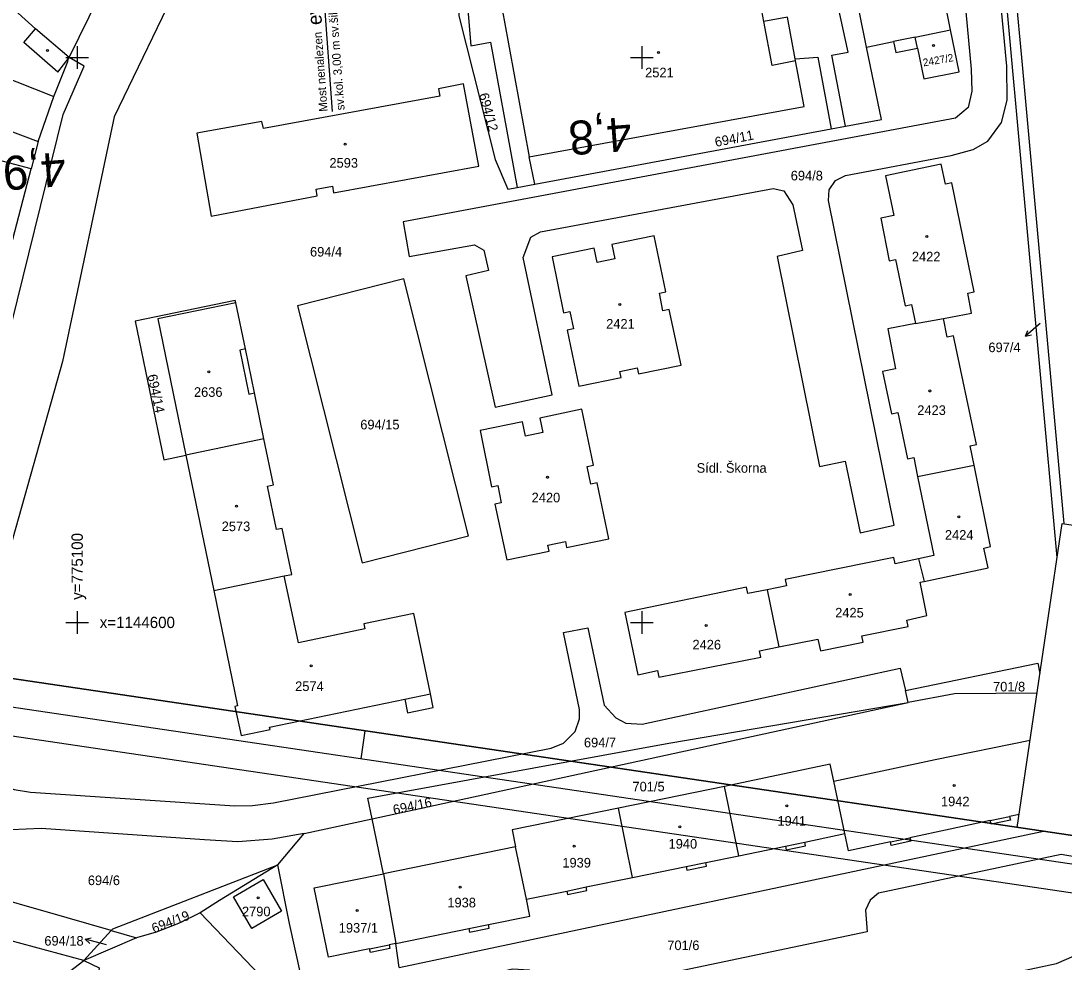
# Model space of a CAD drawing. Extents: x -779302 to -774398, y -1144902 to -1142831.
# Drawn here: x -775110 to -774925.2, y -1144660.1 to -1144493.5 of the extents above; entities that cross this region are included whole.
import ezdxf

# ---------------------------------------------------------------- set-up
doc = ezdxf.new("R2010")
doc.units = 0
for name, color, linetype in [('hektosit - Vrstva 5', 7, 'Continuous'), ('Hranice parcel', 7, 'Continuous'), ('legenda - Vrstva 7', 7, 'Continuous'), ('Parcelní čísla', 7, 'Continuous'), ('Pop  PČ popisy', 7, 'Continuous'), ('Vnitřní kresba', 7, 'Continuous'), ('Vrstva 1', 7, 'Continuous'), ('zjednodus_g_situ-seda - Vrstva 18', 7, 'Continuous'), ('zjednodus_g_situ-seda - Vrstva 7', 7, 'Continuous'), ('Značky budov', 7, 'Continuous')]:
    doc.layers.add(name, color=color, linetype=linetype)

msp = doc.modelspace()

# ---------------------------------------------------------------- linework, layer by layer
at = {"layer": 'hektosit - Vrstva 5'}
for p, q in [((-775100, -1144498), (-775100, -1144502)), ((-775000, -1144498), (-775000, -1144502)), ((-775102, -1144500), (-775098, -1144500)), ((-775002, -1144500), (-774998, -1144500)), ((-775100, -1144598), (-775100, -1144602)), ((-775000, -1144598), (-775000, -1144602)), ((-775102, -1144600), (-775098, -1144600)), ((-775002, -1144600), (-774998, -1144600))]:
    msp.add_line(p, q, dxfattribs=at)
at = {"layer": 'Hranice parcel'}
for p, q in [((-774935.34, -1144472.21), (-774932.82, -1144500)), ((-774926.48, -1144588.49), (-774936.18, -1144481.83)), ((-774932.82, -1144500), (-774925.31, -1144582.51)), ((-775018.98, -1144522.44), (-774966.48, -1144512.63)), ((-774966.48, -1144512.63), (-774963.98, -1144512.17)), ((-775106.9, -1144514.86), (-775108.17, -1144519.73)), ((-775018.98, -1144522.44), (-775019.94, -1144517.62)), ((-775022.07, -1144523.02), (-775018.98, -1144522.44)), ((-774951.55, -1144547.07), (-774946.62, -1144546.23)), ((-775066.94, -1144567.53), (-775080.75, -1144570.41)), ((-775080.75, -1144570.41), (-775075.83, -1144594.37)), ((-774951.18, -1144574.18), (-774941.18, -1144572.17)), ((-774951, -1144588.72), (-774950.02, -1144592.74)), ((-775075.83, -1144594.37), (-775063.33, -1144591.78)), ((-774977.82, -1144594.22), (-774975.76, -1144604.34)), ((-774952.86, -1144614.17), (-774953.35, -1144612.05)), ((-775047.76, -1144634.76), (-774952.86, -1144614.17)), ((-774985.36, -1144629.03), (-775004.17, -1144632.88)), ((-774982.85, -1144641.3), (-774985.36, -1144629.03)), ((-774964.08, -1144637.36), (-774966.05, -1144628.11)), ((-775001.66, -1144645.15), (-775004.17, -1144632.88)), ((-775059.8, -1144637.37), (-775047.76, -1144634.76)), ((-775045.78, -1144644.49), (-775047.76, -1144634.76)), ((-775064.48, -1144642.88), (-775059.8, -1144637.37)), ((-775022.36, -1144639.7), (-775045.78, -1144644.49)), ((-775020.46, -1144649), (-775022.36, -1144639.7)), ((-775045.78, -1144644.49), (-775043.55, -1144656.82)), ((-775098.79, -1144659.85), (-775093.98, -1144654.54)), ((-775093.98, -1144654.54), (-775089.48, -1144655.85)), ((-775043.55, -1144656.82), (-775030.64, -1144654.18)), ((-775089.48, -1144655.85), (-775098.79, -1144659.85)), ((-775042.99, -1144661.05), (-775043.55, -1144656.82))]:
    msp.add_line(p, q, dxfattribs=at)
for points in [[(-774945.13, -1144465.25), (-774941.71, -1144502.06), (-774941.57, -1144505.98), (-774942.23, -1144508.88), (-774944.46, -1144510.75), (-775042.26, -1144529.08), (-775041.21, -1144535.25), (-775029.64, -1144533.2), (-775027.98, -1144534.13), (-775027.15, -1144537.72), (-775031.16, -1144538.67), (-775025.99, -1144561.88), (-775015.89, -1144559.74), (-775021, -1144535.42), (-775019.67, -1144531.82), (-775017.95, -1144530.88), (-774976.76, -1144523.19), (-774974.85, -1144523.59), (-774973.29, -1144526.08), (-774971.56, -1144534.16), (-774976.03, -1144535.26), (-774968.53, -1144572.4), (-774964.04, -1144571.46), (-774961.35, -1144584.12), (-774955.31, -1144582.77), (-774966.99, -1144525.35), (-774966.86, -1144523.45), (-774965.7, -1144521.8), (-774963.95, -1144520.9), (-774945.27, -1144517.35), (-774941.33, -1144516.3), (-774938.75, -1144514.81), (-774936.31, -1144511.55), (-774935.35, -1144507.58), (-774935.39, -1144501.57), (-774939.15, -1144461.66)], [(-774963.98, -1144512.17), (-774966.4, -1144499.6), (-774963.5, -1144499.07), (-774968.82, -1144474.76), (-774974.62, -1144476.02), (-774975.77, -1144475.24), (-774977.53, -1144462.71)], [(-774945.34, -1144495.11), (-774948.39, -1144479.92), (-774944.8, -1144479.21), (-774946.27, -1144472.15), (-774949.81, -1144472.84), (-774950.71, -1144468.34), (-774949.97, -1144468.19), (-774950.38, -1144466.13), (-774951.13, -1144466.27), (-774951.9, -1144462.39), (-774966.83, -1144465.38), (-774970.98, -1144466.22), (-774969.64, -1144472.62)], [(-775031.24, -1144466.92), (-775031.6, -1144474.7), (-775032.41, -1144492.66), (-775025.96, -1144518.08), (-775023.75, -1144523.35), (-775022.07, -1144523.02)], [(-775030.68, -1144466.87), (-775031.45, -1144483.59), (-775030.29, -1144497.96), (-775026.8, -1144497.32), (-775022.07, -1144523.02)], [(-775066.86, -1144469.73), (-775073.3, -1144474.69), (-775076.25, -1144477.78), (-775081.56, -1144485.89), (-775093.44, -1144510.53), (-775102.62, -1144553.8), (-775111.39, -1144585.09), (-775117.05, -1144604.72), (-775118.64, -1144626.24)], [(-774960.24, -1144498.17), (-774965.54, -1144471.8), (-774969.64, -1144472.62)], [(-775101.41, -1144500), (-775094.32, -1144485.56), (-775103.59, -1144480.25)], [(-774972.85, -1144500.27), (-774974.21, -1144492.89), (-774978.42, -1144493.64), (-774980.01, -1144485.11), (-774981.79, -1144485.44), (-774982.01, -1144484.24), (-774984.54, -1144484.75), (-774984.32, -1144485.92), (-775014.34, -1144491.54), (-775014.88, -1144488.6), (-775024.95, -1144490.57), (-775024.42, -1144493.43), (-775019.94, -1144517.62)], [(-775101.41, -1144500), (-775107.35, -1144494.96), (-775114.15, -1144488.83)], [(-774951.2, -1144498.34), (-774951.6, -1144496.4), (-774945.34, -1144495.11)], [(-774951.2, -1144498.34), (-774950.1, -1144503.77), (-774943.85, -1144502.54), (-774945.34, -1144495.11)], [(-774960.24, -1144498.17), (-774955.46, -1144497.19), (-774955.06, -1144499.13), (-774951.2, -1144498.34)], [(-774963.98, -1144512.17), (-774957.59, -1144510.97), (-774960.24, -1144498.17)], [(-775132.39, -1144743.84), (-775130.26, -1144703.04), (-775130.18, -1144647.07), (-775130.3, -1144636.58), (-775130.44, -1144623.61), (-775122.75, -1144592.02), (-775102.48, -1144510.12), (-775098.75, -1144501.58), (-775101.41, -1144500)], [(-775106.9, -1144514.86), (-775104.11, -1144506.94), (-775101.67, -1144500.72), (-775101.58, -1144500.32), (-775101.41, -1144500)], [(-775019.94, -1144517.62), (-774971.3, -1144508.68), (-774972.79, -1144500.6), (-774972.85, -1144500.27)], [(-774972.85, -1144500.27), (-774968.87, -1144499.96), (-774966.48, -1144512.63)], [(-775057.68, -1144523.31), (-775054.81, -1144522.81), (-775054.6, -1144523.96), (-775028.86, -1144519.23), (-775031.57, -1144504.68), (-775036.03, -1144505.59), (-775035.8, -1144506.85), (-775066.98, -1144512.61), (-775067.28, -1144511.33), (-775078.83, -1144513.41), (-775076.29, -1144528.08), (-775057.53, -1144524.49), (-775057.68, -1144523.31)], [(-775126.6, -1144507.49), (-775122.14, -1144509.16), (-775106.9, -1144514.86)], [(-775108.17, -1144519.73), (-775118, -1144517.12), (-775122.7, -1144515.87), (-775124.41, -1144515.34), (-775126.69, -1144514.82), (-775128.59, -1144517.8)], [(-775113.13, -1144538.78), (-775112.12, -1144534.91), (-775108.17, -1144519.73)], [(-774946.62, -1144546.23), (-774941.62, -1144545.26), (-774942.3, -1144541.71), (-774941.17, -1144541.48), (-774945.1, -1144522.18), (-774946.23, -1144522.42), (-774947, -1144518.92), (-774956.89, -1144520.97), (-774955.41, -1144527.99), (-774957.72, -1144528.45), (-774956.22, -1144536), (-774955.08, -1144535.77), (-774953.37, -1144543.99), (-774952.24, -1144543.75), (-774951.55, -1144547.07)], [(-775015.89, -1144535.3), (-775013.86, -1144545.2), (-775012.74, -1144544.97), (-775012.1, -1144548.05), (-775013.23, -1144548.28), (-775011.19, -1144558.19), (-775003.69, -1144556.66), (-775003.91, -1144555.58), (-775000.82, -1144554.95), (-775000.6, -1144556.03), (-774993.08, -1144554.5), (-774995.15, -1144544.6), (-774996.28, -1144544.83), (-774996.91, -1144541.74), (-774995.79, -1144541.5), (-774997.84, -1144531.6), (-775005.32, -1144533.13), (-775004.8, -1144535.68), (-775007.91, -1144536.32), (-775008.43, -1144533.77), (-775015.89, -1144535.3)], [(-775061, -1144543.96), (-775049.56, -1144589.46), (-775030.71, -1144584.69), (-775042.15, -1144539.22), (-775061, -1144543.96)], [(-775071.88, -1144543.41), (-775072, -1144543.05), (-775089.75, -1144546.7), (-775084.65, -1144571.23), (-775080.75, -1144570.41)], [(-775071.88, -1144543.41), (-775085.74, -1144546.29), (-775080.75, -1144570.41)], [(-775066.94, -1144567.53), (-775068.61, -1144559.37), (-775070.2, -1144551.61), (-775071.88, -1144543.41)], [(-774951.55, -1144547.07), (-774956.48, -1144548.05), (-774955.12, -1144555.1), (-774957.41, -1144555.59), (-774955.81, -1144563.06), (-774954.68, -1144562.82), (-774953, -1144571.03), (-774951.87, -1144570.8), (-774951.18, -1144574.18)], [(-774941.18, -1144572.17), (-774941.87, -1144568.75), (-774940.75, -1144568.51), (-774944.82, -1144549.27), (-774945.94, -1144549.5), (-774946.62, -1144546.23)], [(-775025.53, -1144575.76), (-775024.92, -1144578.83), (-775026.04, -1144579.07), (-775023.9, -1144588.95), (-775016.44, -1144587.4), (-775016.66, -1144586.34), (-775013.55, -1144585.69), (-775013.33, -1144586.75), (-775005.88, -1144585.19), (-775007.93, -1144575.29), (-775009.06, -1144575.52), (-775009.7, -1144572.42), (-775008.57, -1144572.18), (-775010.63, -1144562.26), (-775018.09, -1144563.83), (-775017.55, -1144566.37), (-775020.64, -1144567.02), (-775021.17, -1144564.48), (-775028.63, -1144566.06), (-775026.65, -1144575.98), (-775025.53, -1144575.76)], [(-775063.33, -1144591.78), (-775062.01, -1144591.5), (-775063.68, -1144583.36), (-775064.72, -1144583.57), (-775066.3, -1144575.87), (-775065.26, -1144575.66), (-775066.94, -1144567.53)], [(-774950.02, -1144592.74), (-774938.71, -1144590.35), (-774939.45, -1144586.84), (-774938.26, -1144586.58), (-774941.18, -1144572.17)], [(-774951.18, -1144574.18), (-774948.33, -1144588.17), (-774951, -1144588.72)], [(-774951, -1144588.72), (-774955.16, -1144589.62), (-774955.39, -1144588.5), (-774974.64, -1144592.38), (-774974.41, -1144593.52), (-774977.82, -1144594.22)], [(-775075.83, -1144594.37), (-775071.62, -1144614.78), (-775072.06, -1144614.87), (-775070.99, -1144620.02), (-775065.84, -1144618.96), (-775065.93, -1144618.52), (-775042.01, -1144613.59), (-775041.52, -1144615.98), (-775036.95, -1144615.04), (-775037.44, -1144612.65), (-775040.4, -1144598.45), (-775049.27, -1144600.27), (-775049.09, -1144601.14), (-775060.81, -1144603.59), (-775063.33, -1144591.78)], [(-774977.82, -1144594.22), (-774981.23, -1144594.91), (-774981.46, -1144593.78), (-775003.02, -1144598.27), (-775000.75, -1144609.29), (-774997.23, -1144608.54), (-774996.99, -1144609.71), (-774978.94, -1144606.14), (-774979.16, -1144605.01), (-774975.76, -1144604.34)], [(-774975.76, -1144604.34), (-774968.83, -1144602.94), (-774968.37, -1144605.03), (-774960.85, -1144603.5), (-774961.08, -1144602.37), (-774952.85, -1144600.73), (-774953.08, -1144599.6), (-774949.58, -1144598.79), (-774950.76, -1144592.9), (-774950.02, -1144592.74)], [(-775118.64, -1144626.24), (-775117.63, -1144626.76), (-775114.02, -1144628.64), (-775111.15, -1144629.56), (-775108.25, -1144630.03), (-775072.11, -1144632.49), (-775068.93, -1144632.43), (-775065.26, -1144631.94), (-775016.08, -1144622.26), (-775013.91, -1144621.39), (-775011.81, -1144619.33), (-775011.07, -1144617.04), (-775011.04, -1144615.41), (-775013.87, -1144601.8), (-775009.6, -1144600.96), (-775006.67, -1144614.66), (-775004.63, -1144616.87), (-775002.85, -1144617.85), (-774999.95, -1144618.02), (-774954.26, -1144608.09), (-774953.35, -1144612.05)], [(-774953.35, -1144612.05), (-774929.9, -1144607.21), (-774929.52, -1144609.03)], [(-775047.76, -1144634.76), (-775048.51, -1144631.09), (-774995.24, -1144621.4), (-774952.86, -1144614.17)], [(-774930.03, -1144612.52), (-774944.66, -1144612.65), (-774952.86, -1144614.17)], [(-774966.05, -1144628.11), (-774948.07, -1144624.29), (-774931.26, -1144620.84)], [(-774966.05, -1144628.11), (-774966.68, -1144625.12), (-774985.36, -1144629.03)], [(-775004.17, -1144632.88), (-775022.97, -1144636.72), (-775022.36, -1144639.7)], [(-774933.21, -1144634), (-774934.9, -1144634.36), (-774934.76, -1144634.99), (-774938.19, -1144635.72), (-774938.32, -1144635.09), (-774945.45, -1144636.6), (-774952.55, -1144638.11), (-774952.41, -1144638.74), (-774955.84, -1144639.47), (-774955.98, -1144638.84), (-774963.43, -1144640.42), (-774964.08, -1144637.36)], [(-775059.8, -1144637.37), (-775065.48, -1144638.36), (-775071.57, -1144638.81), (-775077.45, -1144638.5), (-775106.37, -1144636.49), (-775114.39, -1144636.85), (-775117.34, -1144637.41), (-775119.17, -1144638.22), (-775119.54, -1144638.38)], [(-775042.99, -1144661.05), (-774928.91, -1144636.97)], [(-774982.85, -1144641.3), (-774974.6, -1144639.61), (-774974.48, -1144640.24), (-774971.03, -1144639.53), (-774971.16, -1144638.91), (-774964.08, -1144637.36)], [(-774945.87, -1144666.63), (-774946.32, -1144664.58), (-774926.62, -1144660.38), (-774922.11, -1144658.43), (-774915.55, -1144654.1), (-774913.6, -1144651.77), (-774913.25, -1144649.95), (-774914.27, -1144647.26), (-774916.78, -1144644.31), (-774920.05, -1144642.11), (-774925.78, -1144641.08), (-774958.14, -1144647.94), (-774959.58, -1144649.16), (-774960.39, -1144650.94), (-774960.12, -1144654.79), (-775016.68, -1144666.62), (-775017.69, -1144663.53), (-775019.98, -1144661.57), (-775022.9, -1144661.4), (-775041.66, -1144665.85), (-775042.33, -1144666.27)], [(-775001.66, -1144645.15), (-774992.16, -1144643.21), (-774992.03, -1144643.83), (-774988.58, -1144643.13), (-774988.71, -1144642.5), (-774982.85, -1144641.3)], [(-775109.1, -1144687.73), (-775060.52, -1144676.74), (-775057.4, -1144676.03), (-775062.41, -1144653.28), (-775064.48, -1144642.88)], [(-775093.98, -1144654.54), (-775093.7, -1144654.23), (-775064.48, -1144642.88)], [(-775064.48, -1144642.88), (-775074.81, -1144649.2), (-775078.24, -1144651.43)], [(-775072.34, -1144648.55), (-775067.09, -1144645.52), (-775063.82, -1144651.12), (-775069.1, -1144654.17), (-775072.34, -1144648.55)], [(-775043.55, -1144656.82), (-775044.77, -1144657.07), (-775044.64, -1144657.7), (-775048.09, -1144658.41), (-775048.22, -1144657.78), (-775055.51, -1144659.27), (-775058.02, -1144647), (-775045.78, -1144644.49)], [(-775020.46, -1144649), (-775013.32, -1144647.54), (-775013.19, -1144648.16), (-775009.73, -1144647.46), (-775009.86, -1144646.83), (-775001.66, -1144645.15)], [(-775093.98, -1144654.54), (-775101.75, -1144652.28), (-775119.15, -1144647.36)], [(-775030.64, -1144654.18), (-775030.51, -1144654.81), (-775027.05, -1144654.1), (-775027.18, -1144653.47), (-775019.85, -1144651.97), (-775020.46, -1144649)], [(-775098.79, -1144659.85), (-775096.1, -1144661.12), (-775097.27, -1144672.41), (-775087.08, -1144673.44), (-775085.07, -1144673.62), (-775073.05, -1144674.86), (-775073.16, -1144675.85), (-775070.19, -1144676.15), (-775070.09, -1144675.16), (-775067.06, -1144675.47), (-775062.14, -1144668.17), (-775078.24, -1144651.43)], [(-775078.24, -1144651.43), (-775082.04, -1144653.3), (-775086, -1144654.83), (-775089.48, -1144655.85)], [(-775109.1, -1144687.73), (-775109.23, -1144685.55), (-775109.2, -1144677.28), (-775108.63, -1144672.96), (-775108.02, -1144671.58), (-775106.96, -1144669.22), (-775104.75, -1144665.58), (-775102.1, -1144662.36), (-775098.79, -1144659.85)]]:
    msp.add_lwpolyline(points, dxfattribs=at)
at = {"layer": 'legenda - Vrstva 7'}
msp.add_lwpolyline([(-774851.19, -1144648.48), (-774933.55, -1144636.29), (-774925.58, -1144582.47), (-774843.23, -1144594.66)], close=True, dxfattribs=at)
at = {"layer": 'Pop  PČ popisy'}
for p, q in [((-774929.82, -1144547.39), (-774932.08, -1144549.36)), ((-774929.46, -1144547.08), (-774929.82, -1144547.39)), ((-774932.08, -1144549.36), (-774931.66, -1144548.32)), ((-774932.08, -1144549.36), (-774931, -1144549.08)), ((-775098.6, -1144656.08), (-775097.51, -1144655.84)), ((-775095.69, -1144656.81), (-775098.6, -1144656.08)), ((-775098.6, -1144656.08), (-775097.75, -1144656.81)), ((-775094.81, -1144657.04), (-775095.69, -1144656.81))]:
    msp.add_line(p, q, dxfattribs=at)
at = {"layer": 'Vnitřní kresba'}
for p, q in [((-774976.95, -1144501.46), (-774978.42, -1144493.64)), ((-775109.45, -1144497.38), (-775107.35, -1144494.96)), ((-775103.4, -1144502.63), (-775109.45, -1144497.38)), ((-774951.6, -1144496.4), (-774955.46, -1144497.19)), ((-775118.94, -1144501.06), (-775104.11, -1144506.94)), ((-775103.4, -1144502.63), (-775101.41, -1144500)), ((-774972.79, -1144500.6), (-774976.95, -1144501.46)), ((-775070.2, -1144551.61), (-775071.22, -1144551.82)), ((-775071.22, -1144551.82), (-775069.63, -1144559.58)), ((-775069.63, -1144559.58), (-775068.61, -1144559.37)), ((-775042.01, -1144613.59), (-775037.44, -1144612.65)), ((-774938.32, -1144635.09), (-774934.9, -1144634.36)), ((-774955.98, -1144638.84), (-774952.55, -1144638.11)), ((-774974.6, -1144639.61), (-774971.16, -1144638.91)), ((-774992.16, -1144643.21), (-774988.71, -1144642.5)), ((-775013.32, -1144647.54), (-775009.86, -1144646.83)), ((-775098.79, -1144659.85), (-775118.62, -1144654.49)), ((-775030.64, -1144654.18), (-775027.18, -1144653.47)), ((-775048.22, -1144657.78), (-775044.77, -1144657.07))]:
    msp.add_line(p, q, dxfattribs=at)
at = {"layer": 'Vrstva 1'}
msp.add_line((-775049.04, -1144619.2), (-775049.77, -1144624.14), dxfattribs=at)
for points in [[(-774799.29, -1144366.04), (-776045.7, -1144181.56), (-776089.18, -1144475.34), (-774842.77, -1144659.83)], [(-774846.98, -1144654.15), (-776083.5, -1144471.13), (-776041.48, -1144187.23), (-774804.97, -1144370.25)], [(-774810.64, -1144374.46), (-775834.48, -1144222.92), (-775875.04, -1144496.94), (-774851.19, -1144648.48)], [(-774851.19, -1144648.48), (-775875.04, -1144496.94), (-775834.48, -1144222.92), (-774810.64, -1144374.46)]]:
    msp.add_lwpolyline(points, close=True, dxfattribs=at)
at = {"layer": 'zjednodus_g_situ-seda - Vrstva 18'}
msp.add_line((-775054.76, -1144509.56), (-775059.35, -1144448.73), dxfattribs=at)
at = {"layer": 'Značky budov'}
for centre in [(-774948.37, -1144497.89), (-775105.25, -1144498.77), (-774997.06, -1144499.11), (-775052.56, -1144515.37), (-774949.57, -1144531.68), (-775003.89, -1144543.75), (-775076.69, -1144555.64), (-774949, -1144559.04), (-775016.71, -1144574.32), (-775071.78, -1144579.41), (-774943.91, -1144581.3), (-774963.15, -1144595.07), (-774988.61, -1144600.54), (-775058.58, -1144607.71), (-774944.71, -1144628.89), (-774974.36, -1144632.45), (-774993.31, -1144636.16), (-775012.01, -1144639.59), (-775032.2, -1144646.85), (-775067.97, -1144648.75), (-775050.42, -1144650.99)]:
    msp.add_circle(centre, 0.175, dxfattribs=at)

# ---------------------------------------------------------------- texts
at = {"layer": 'hektosit - Vrstva 5'}
msp.add_text('y=775100', height=2, rotation=90, dxfattribs=at).set_placement((-775099, -1144596))
msp.add_text('x=1144600', height=2, dxfattribs=at).set_placement((-775096, -1144601))
at = {"layer": 'Parcelní čísla'}
for s, height, rotation, p in [('2427/2', 1.337, 10, (-774950.13, -1144501.6)), ('694/12', 1.7, 285, (-775028.87, -1144506.54)), ('694/11', 1.7, 11, (-774986.92, -1144515.85)), ('694/14', 1.7, 282, (-775087.56, -1144556.27)), ('694/16', 1.7, 12, (-775043.89, -1144634.04)), ('694/19', 1.7, 21, (-775086.42, -1144655.02))]:
    msp.add_text(s, height=height, rotation=rotation, dxfattribs=at).set_placement(p)
for s, p in [('2521', (-774999.43, -1144503.53)), ('2593', (-775055.33, -1144519.52)), ('694/8', (-774973.65, -1144521.77)), ('694/4', (-775058.77, -1144535.25)), ('2422', (-774952.2, -1144536.11)), ('2421', (-775006.33, -1144548)), ('697/4', (-774938.65, -1144552.17)), ('2636', (-775079.32, -1144560.08)), ('2423', (-774951.25, -1144563.28)), ('694/15', (-775049.87, -1144565.84)), ('2420', (-775019.53, -1144578.75)), ('2573', (-775074.41, -1144583.85)), ('2424', (-774946.35, -1144585.36)), ('2425', (-774965.78, -1144599.13)), ('2426', (-774991.05, -1144604.79)), ('2574', (-775061.4, -1144612.15)), ('701/8', (-774937.83, -1144612.22)), ('694/7', (-775010.27, -1144622.11)), ('701/5', (-775001.67, -1144629.91)), ('1942', (-774947.05, -1144632.54)), ('1941', (-774976, -1144635.99)), ('1940', (-774995.28, -1144640.04)), ('1939', (-775014.09, -1144643.38)), ('694/6', (-775098.11, -1144646.5)), ('1938', (-775034.45, -1144650.44)), ('2790', (-775070.82, -1144652.01)), ('1937/1', (-775053.68, -1144654.91)), ('694/18', (-775105.81, -1144657.21)), ('701/6', (-774995.51, -1144658))]:
    msp.add_text(s, height=1.7, dxfattribs=at).set_placement(p)
at = {"layer": 'Pop  PČ popisy'}
msp.add_text('Sídl. Škorna', height=1.7, dxfattribs=at).set_placement((-774990.31, -1144573.51))
at = {"layer": 'zjednodus_g_situ-seda - Vrstva 18'}
for s, height, p in [('evid. km 4,848', 2.5, (-775056.63, -1144494.19)), ('sv.kol. 3,00 m sv.šik. 3,25 m vol.v. 2,90 m', 1.5, (-775052.64, -1144509.32)), ('Most nenalezen', 1.5, (-775055.64, -1144509.55))]:
    msp.add_text(s, height=height, rotation=94.3166, dxfattribs=at).set_placement(p)
at = {"layer": 'zjednodus_g_situ-seda - Vrstva 7'}
for s, rotation, p in [('4,8', 184.305, (-775002.05, -1144510.51)), ('4,9', 184.3156, (-775102.23, -1144516.74))]:
    msp.add_text(s, height=6, rotation=rotation, dxfattribs=at).set_placement(p)

doc.saveas('drawing.dxf')
